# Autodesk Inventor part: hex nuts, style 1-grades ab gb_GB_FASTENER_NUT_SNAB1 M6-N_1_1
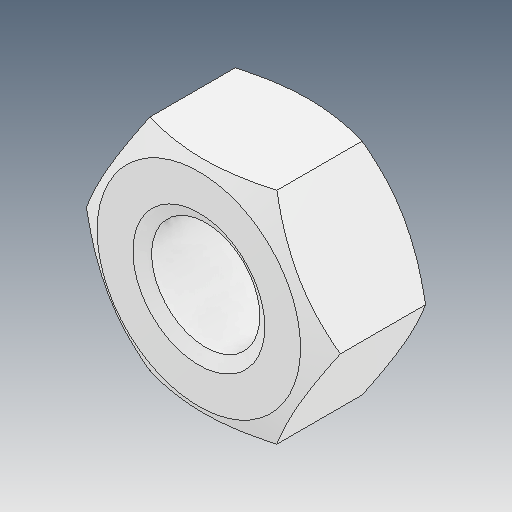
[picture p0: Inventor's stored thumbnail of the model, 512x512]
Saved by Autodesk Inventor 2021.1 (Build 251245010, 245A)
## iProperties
Created: 2021-05
Part Number: hex nuts, style 1-grades ab gb_GB_FASTENER_NUT_SNAB1 M6-N_1_1
Material: Ogólny
Document SubType Name: Modeling
Designer: user
Density: 1 g/cm^3
Appearance: Domyślna
Author: user
Revision Number: ÈÎºÎ
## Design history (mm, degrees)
feature "ÊäÈë1"
node "Bryła1"
